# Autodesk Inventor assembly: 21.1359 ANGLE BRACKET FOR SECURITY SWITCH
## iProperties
Created: 2007-05
Part Number: 21.1359 ANGLE BRACKET FOR SECURITY SWITCH
Document SubType Name: Assembly
Designer: Andy Moles
Author: Andy Moles
